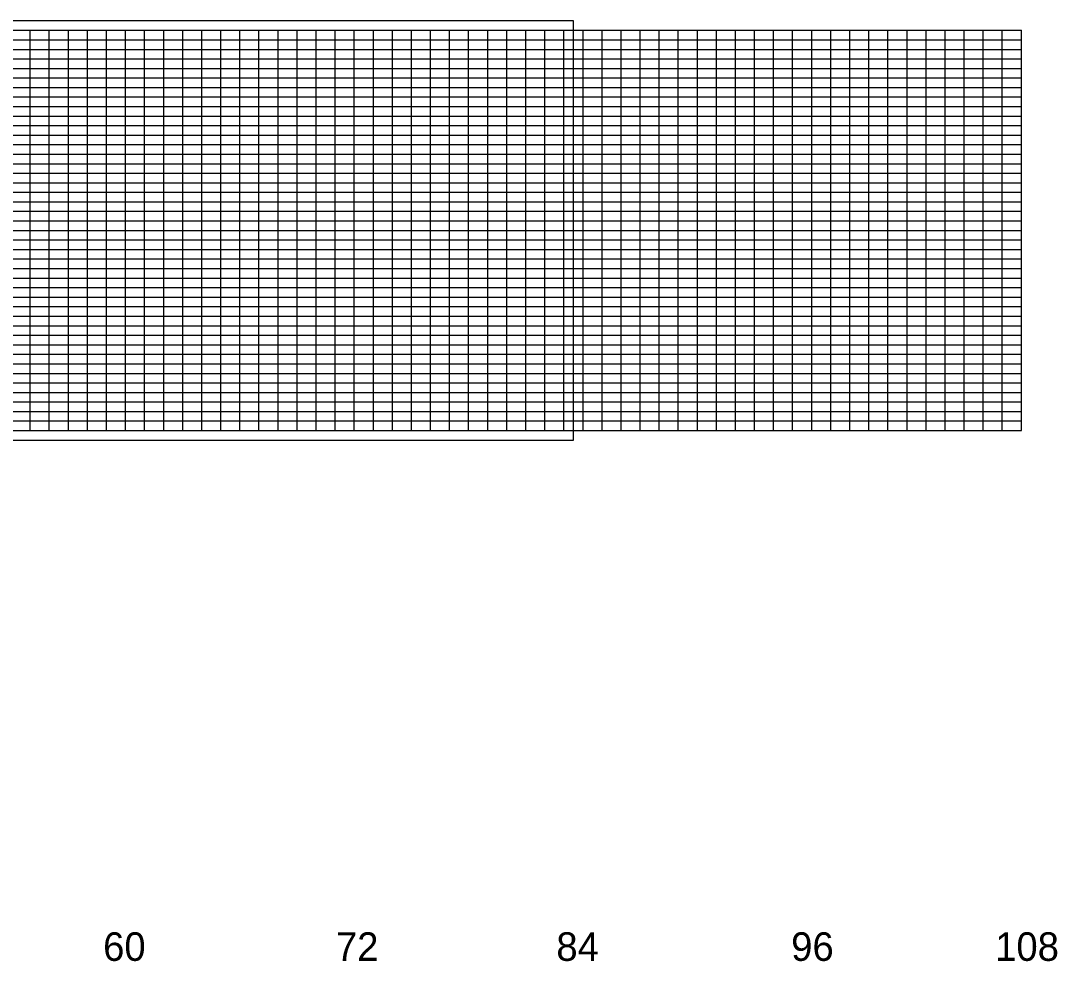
# Model space of a CAD drawing. Extents: x 1950433 to 1956806, y 750939 to 777666.
# Drawn here: x 1954081 to 1956801, y 762072 to 764539 of the extents above; entities that cross this region are included whole.
import ezdxf

# ---------------------------------------------------------------- set-up
doc = ezdxf.new("R2010")
doc.units = 0
doc.layers.add('RD_PD_WallFill', color=7, linetype='Continuous')
doc.layers.add('RD_SHT_IplotShp', color=7, linetype='Continuous')

msp = doc.modelspace()

# ---------------------------------------------------------------- linework, layer by layer
at = {"layer": 'RD_PD_WallFill'}
for p, q in [((1951356.4, 764514.1), (1956706.4, 764514.2)), ((1951806.4, 764489.1), (1956706.4, 764489.1)), ((1954106.4, 763464.2), (1954106.4, 764514.2)), ((1954156.4, 763464.2), (1954156.4, 764514.2)), ((1954206.4, 763464.2), (1954206.4, 764514.2)), ((1954256.4, 763464.2), (1954256.4, 764514.2)), ((1954306.4, 763464.2), (1954306.4, 764514.2)), ((1954356.4, 763464.2), (1954356.4, 764514.2)), ((1954406.4, 763464.2), (1954406.4, 764514.2)), ((1954456.4, 763464.1), (1954456.4, 764514.2)), ((1954506.4, 763464.2), (1954506.4, 764514.2)), ((1954556.4, 763464.2), (1954556.4, 764514.2)), ((1954606.4, 763464.2), (1954606.4, 764514.2)), ((1954656.4, 763464.2), (1954656.4, 764514.2)), ((1954706.4, 763464.2), (1954706.4, 764514.2)), ((1954756.4, 763464.1), (1954756.4, 764514.2)), ((1954806.4, 763464.1), (1954806.4, 764514.2)), ((1954856.4, 763464.2), (1954856.4, 764514.2)), ((1954906.4, 763464.2), (1954906.4, 764514.2)), ((1954956.4, 763464.2), (1954956.4, 764514.2)), ((1955006.4, 763464.2), (1955006.4, 764514.2)), ((1955056.4, 763464.2), (1955056.4, 764514.2)), ((1955106.4, 763464.2), (1955106.4, 764514.2)), ((1955156.4, 763464.2), (1955156.4, 764514.2)), ((1955206.4, 763464.2), (1955206.4, 764514.2)), ((1955256.4, 763464.2), (1955256.4, 764514.2)), ((1955306.4, 763464.2), (1955306.4, 764514.2)), ((1955356.4, 763464.2), (1955356.4, 764514.2)), ((1955406.4, 763464.2), (1955406.4, 764514.2)), ((1955456.4, 763464.2), (1955456.4, 764514.2)), ((1955506.4, 763464.2), (1955506.4, 764514.2)), ((1955556.4, 763464.2), (1955556.4, 764514.2)), ((1955606.4, 763464.2), (1955606.4, 764514.2)), ((1955656.4, 763464.2), (1955656.4, 764514.2)), ((1955706.4, 763464.2), (1955706.4, 764514.2)), ((1955756.4, 763464.2), (1955756.4, 764514.2)), ((1955806.4, 763464.2), (1955806.4, 764514.2)), ((1955856.4, 763464.2), (1955856.4, 764514.2)), ((1955906.4, 763464.2), (1955906.4, 764514.2)), ((1955956.4, 763464.2), (1955956.4, 764514.2)), ((1956006.4, 763464.2), (1956006.4, 764514.2)), ((1956056.4, 763464.2), (1956056.4, 764514.2)), ((1956106.4, 763464.2), (1956106.4, 764514.2)), ((1956156.4, 763464.2), (1956156.4, 764514.2)), ((1956206.4, 763464.2), (1956206.4, 764514.2)), ((1956256.4, 763464.2), (1956256.4, 764514.2)), ((1956306.4, 763464.2), (1956306.4, 764514.2)), ((1956356.4, 763464.2), (1956356.4, 764514.2)), ((1956406.4, 763464.2), (1956406.4, 764514.2)), ((1956456.4, 763464.2), (1956456.4, 764514.2)), ((1956506.4, 763464.2), (1956506.4, 764514.2)), ((1956556.4, 763464.2), (1956556.4, 764514.2)), ((1956606.4, 763464.2), (1956606.4, 764514.2)), ((1956656.4, 763464.2), (1956656.4, 764514.2)), ((1956706.4, 763464.2), (1956706.4, 764514.2)), ((1951806.4, 764464.1), (1956706.4, 764464.1)), ((1951806.4, 764439.1), (1956706.4, 764439.1)), ((1951806.4, 764414.2), (1956706.4, 764414.1)), ((1951806.4, 764389.1), (1956706.4, 764389.2)), ((1951356.4, 764364.1), (1956706.4, 764364.1)), ((1951356.4, 764339.1), (1956706.4, 764339.1)), ((1951356.4, 764314.1), (1956706.4, 764314.2)), ((1951356.4, 764289.2), (1956706.4, 764289.1)), ((1951356.4, 764264.2), (1956706.4, 764264.2)), ((1951356.4, 764239.1), (1956706.4, 764239.1)), ((1951356.4, 764214.1), (1956706.4, 764214.1)), ((1951356.4, 764189.2), (1956706.4, 764189.1)), ((1951356.4, 764164.1), (1956706.4, 764164.1)), ((1951356.4, 764139.2), (1956706.4, 764139.1)), ((1951356.4, 764114.1), (1956706.4, 764114.1)), ((1951356.4, 764089.1), (1956706.4, 764089.2)), ((1951356.4, 764064.1), (1956706.4, 764064.1)), ((1951356.4, 764039.1), (1956706.4, 764039.2)), ((1951356.4, 764014.1), (1956706.4, 764014.1)), ((1951356.4, 763989.1), (1956706.4, 763989.1)), ((1951356.4, 763964.2), (1956706.4, 763964.1)), ((1951356.4, 763939.1), (1956706.4, 763939.1)), ((1951356.4, 763914.1), (1956706.4, 763914.1)), ((1951356.4, 763889.1), (1956706.4, 763889.1)), ((1951356.4, 763864.1), (1956706.4, 763864.2)), ((1951356.4, 763839.1), (1956706.4, 763839.1)), ((1951356.4, 763814.1), (1956706.4, 763814.1)), ((1951356.4, 763789.1), (1956706.4, 763789.1)), ((1951356.4, 763764.1), (1956706.4, 763764.1)), ((1951356.4, 763739.1), (1956706.4, 763739.1)), ((1951356.4, 763714.1), (1956706.4, 763714.1)), ((1951356.4, 763689.1), (1956706.4, 763689.1)), ((1951356.4, 763664.1), (1956706.4, 763664.1)), ((1951356.4, 763639.1), (1956706.4, 763639.1)), ((1951356.4, 763614.1), (1956706.4, 763614.1)), ((1951356.4, 763589.1), (1956706.4, 763589.1)), ((1951356.4, 763564.1), (1956706.4, 763564.1)), ((1951356.4, 763539.1), (1956706.4, 763539.1)), ((1951356.4, 763514.1), (1956706.4, 763514.1)), ((1951406.4, 763489.1), (1956706.4, 763489.1)), ((1951356.4, 763464.1), (1956706.4, 763464.1))]:
    msp.add_line(p, q, dxfattribs=at)
at = {"layer": 'RD_SHT_IplotShp'}
msp.add_lwpolyline([(1951331.4, 763439.1), (1955531.4, 763439.1), (1955531.4, 764539.1), (1951331.4, 764539.1)], close=True, dxfattribs=at)

# ---------------------------------------------------------------- texts
at = {"layer": 'RD_PD_WallFill'}
for s, p in [('60', (1954297.5, 762072.8)), ('72', (1954908.2, 762072.8)), ('84', (1955486.5, 762072.8)), ('96', (1956102.5, 762072.8)), ('108', (1956637.6, 762072.8))]:
    msp.add_text(s, height=75, dxfattribs=at).set_placement(p)

doc.saveas('drawing.dxf')
